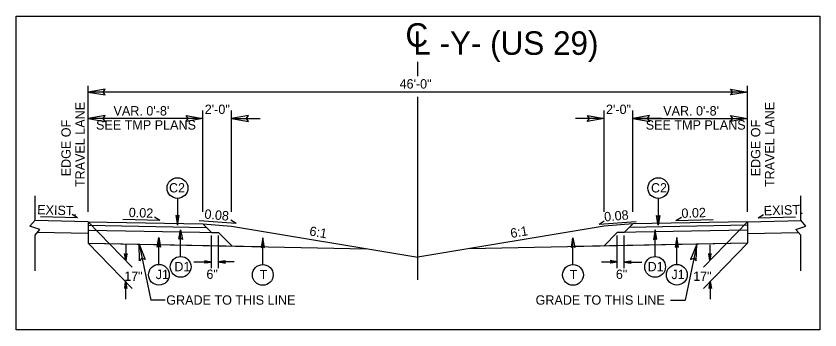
# Model space of a CAD drawing. Extents: x 1901582 to 1902252, y 193723 to 194156.
# Drawn here: x 1902149.6 to 1902205.7, y 193879 to 193901 of the extents above; entities that cross this region are included whole.
import ezdxf

# ---------------------------------------------------------------- set-up
doc = ezdxf.new("R2010")
doc.units = 0
for name, color, linetype in [('Old_Level_1', 7, 'Continuous'), ('Old_Level_11', 7, 'Continuous'), ('Old_Level_2', 7, 'Continuous'), ('Old_Level_20', 7, 'Continuous'), ('Prop Dimension', 7, 'Continuous'), ('Typical Pavement Slope Information CELL', 7, 'Continuous'), ('Typical Slope Point Local CELL', 7, 'Continuous'), ('Typical Terminator CELL', 7, 'Continuous'), ('Typical Text Asphalt at Bridge Approach CELL', 7, 'Continuous'), ('Typical Text Centerline CELL', 7, 'Continuous')]:
    doc.layers.add(name, color=color, linetype=linetype)

msp = doc.modelspace()

# ---------------------------------------------------------------- linework, layer by layer
at = {"layer": 'Old_Level_1'}
for p, q in [((1902164.598, 193893.8), (1902166.598, 193893.8)), ((1902190.598, 193893.8), (1902188.598, 193893.8)), ((1902194.598, 193893.8), (1902192.598, 193893.8)), ((1902154.598, 193886.59), (1902150.856, 193886.665)), ((1902200.599, 193886.59), (1902204.341, 193886.665)), ((1902154.598, 193886.59), (1902154.598, 193885.09)), ((1902154.598, 193886.59), (1902162.598, 193886.43)), ((1902154.598, 193886.59), (1902157.667, 193883.42)), ((1902154.598, 193886.34), (1902162.853, 193886.175)), ((1902162.598, 193886.43), (1902163.194, 193885.835)), ((1902162.598, 193886.43), (1902164.598, 193886.27)), ((1902164.598, 193886.27), (1902177.598, 193884.103)), ((1902190.599, 193886.27), (1902177.598, 193884.103)), ((1902192.599, 193886.43), (1902190.599, 193886.27)), ((1902192.599, 193886.43), (1902192.003, 193885.835)), ((1902200.599, 193886.34), (1902192.344, 193886.175)), ((1902200.599, 193886.59), (1902192.599, 193886.43)), ((1902200.599, 193886.59), (1902197.53, 193883.42)), ((1902200.599, 193886.59), (1902200.599, 193885.09)), ((1902154.598, 193885.756), (1902151.041, 193885.828)), ((1902154.598, 193886.007), (1902163.694, 193885.825)), ((1902163.194, 193885.835), (1902163.694, 193885.825)), ((1902163.694, 193885.825), (1902164.629, 193884.889)), ((1902191.503, 193885.825), (1902190.568, 193884.889)), ((1902200.599, 193886.007), (1902191.503, 193885.825)), ((1902192.003, 193885.835), (1902191.503, 193885.825)), ((1902200.599, 193885.756), (1902204.156, 193885.828)), ((1902154.598, 193885.09), (1902174.009, 193884.702)), ((1902154.598, 193885.09), (1902166.629, 193884.849)), ((1902154.598, 193885.09), (1902157.667, 193881.92)), ((1902158.136, 193885.019), (1902158.954, 193881.11)), ((1902200.599, 193885.09), (1902181.188, 193884.702)), ((1902200.599, 193885.09), (1902188.568, 193884.849)), ((1902197.061, 193885.019), (1902196.243, 193881.11)), ((1902200.599, 193885.09), (1902197.53, 193881.92)), ((1902157.218, 193884.972), (1902157.218, 193883.884)), ((1902197.979, 193884.972), (1902197.979, 193883.884)), ((1902157.218, 193883.884), (1902157.133, 193884.361)), ((1902157.145, 193884.352), (1902157.218, 193883.884)), ((1902157.218, 193883.884), (1902157.158, 193884.343)), ((1902157.17, 193884.335), (1902157.218, 193883.884)), ((1902157.218, 193883.884), (1902157.182, 193884.326)), ((1902157.194, 193884.317), (1902157.218, 193883.884)), ((1902157.218, 193883.884), (1902157.206, 193884.308)), ((1902157.218, 193883.884), (1902157.302, 193884.361)), ((1902157.218, 193883.884), (1902157.29, 193884.352)), ((1902157.278, 193884.343), (1902157.218, 193883.884)), ((1902157.218, 193883.884), (1902157.266, 193884.335)), ((1902157.254, 193884.326), (1902157.218, 193883.884)), ((1902157.218, 193883.884), (1902157.242, 193884.317)), ((1902157.23, 193884.308), (1902157.218, 193883.884)), ((1902157.218, 193884.299), (1902157.218, 193883.884)), ((1902163.694, 193883.786), (1902164.171, 193883.87)), ((1902163.694, 193883.786), (1902164.162, 193883.859)), ((1902191.503, 193883.786), (1902191.026, 193883.87)), ((1902191.503, 193883.786), (1902191.035, 193883.859)), ((1902197.979, 193883.884), (1902197.895, 193884.361)), ((1902197.979, 193883.884), (1902197.907, 193884.352)), ((1902197.919, 193884.343), (1902197.979, 193883.884)), ((1902197.979, 193883.884), (1902197.931, 193884.335)), ((1902197.943, 193884.326), (1902197.979, 193883.884)), ((1902197.979, 193883.884), (1902197.955, 193884.317)), ((1902197.967, 193884.308), (1902197.979, 193883.884)), ((1902197.979, 193883.884), (1902198.064, 193884.361)), ((1902198.052, 193884.352), (1902197.979, 193883.884)), ((1902197.979, 193883.884), (1902198.039, 193884.343)), ((1902198.027, 193884.335), (1902197.979, 193883.884)), ((1902197.979, 193883.884), (1902198.015, 193884.326)), ((1902198.003, 193884.317), (1902197.979, 193883.884)), ((1902197.979, 193883.884), (1902197.991, 193884.308)), ((1902197.979, 193884.299), (1902197.979, 193883.884)), ((1902163.194, 193883.769), (1902161.968, 193883.769)), ((1902163.194, 193883.769), (1902162.716, 193883.854)), ((1902163.194, 193883.769), (1902162.716, 193883.685)), ((1902162.726, 193883.842), (1902163.194, 193883.769)), ((1902163.194, 193883.769), (1902162.726, 193883.697)), ((1902163.194, 193883.769), (1902162.734, 193883.83)), ((1902162.734, 193883.71), (1902163.194, 193883.769)), ((1902162.744, 193883.818), (1902163.194, 193883.769)), ((1902163.194, 193883.769), (1902162.744, 193883.722)), ((1902163.194, 193883.769), (1902162.752, 193883.805)), ((1902162.752, 193883.734), (1902163.194, 193883.769)), ((1902162.76, 193883.793), (1902163.194, 193883.769)), ((1902163.194, 193883.769), (1902162.76, 193883.746)), ((1902163.194, 193883.769), (1902162.769, 193883.781)), ((1902162.769, 193883.758), (1902163.194, 193883.769)), ((1902164.153, 193883.847), (1902163.694, 193883.786)), ((1902163.694, 193883.786), (1902164.145, 193883.835)), ((1902164.136, 193883.822), (1902163.694, 193883.786)), ((1902163.694, 193883.786), (1902164.127, 193883.81)), ((1902164.118, 193883.798), (1902163.694, 193883.786)), ((1902164.782, 193883.786), (1902163.694, 193883.786)), ((1902163.694, 193883.786), (1902164.171, 193883.702)), ((1902164.162, 193883.713), (1902163.694, 193883.786)), ((1902163.694, 193883.786), (1902164.153, 193883.727)), ((1902164.145, 193883.739), (1902163.694, 193883.786)), ((1902163.694, 193883.786), (1902164.136, 193883.751)), ((1902164.127, 193883.762), (1902163.694, 193883.786)), ((1902163.694, 193883.786), (1902164.118, 193883.774)), ((1902164.109, 193883.786), (1902163.694, 193883.786)), ((1902190.415, 193883.786), (1902191.503, 193883.786)), ((1902191.503, 193883.786), (1902191.026, 193883.702)), ((1902191.035, 193883.713), (1902191.503, 193883.786)), ((1902191.044, 193883.847), (1902191.503, 193883.786)), ((1902191.503, 193883.786), (1902191.044, 193883.727)), ((1902191.503, 193883.786), (1902191.052, 193883.835)), ((1902191.052, 193883.739), (1902191.503, 193883.786)), ((1902191.061, 193883.822), (1902191.503, 193883.786)), ((1902191.503, 193883.786), (1902191.061, 193883.751)), ((1902191.503, 193883.786), (1902191.07, 193883.81)), ((1902191.07, 193883.762), (1902191.503, 193883.786)), ((1902191.079, 193883.798), (1902191.503, 193883.786)), ((1902191.503, 193883.786), (1902191.079, 193883.774)), ((1902191.088, 193883.786), (1902191.503, 193883.786)), ((1902192.003, 193883.769), (1902192.481, 193883.854)), ((1902192.471, 193883.842), (1902192.003, 193883.769)), ((1902192.003, 193883.769), (1902192.463, 193883.83)), ((1902192.453, 193883.818), (1902192.003, 193883.769)), ((1902192.003, 193883.769), (1902192.445, 193883.805)), ((1902192.437, 193883.793), (1902192.003, 193883.769)), ((1902192.003, 193883.769), (1902192.428, 193883.781)), ((1902192.003, 193883.769), (1902192.481, 193883.685)), ((1902192.428, 193883.758), (1902192.003, 193883.769)), ((1902192.003, 193883.769), (1902192.437, 193883.746)), ((1902192.445, 193883.734), (1902192.003, 193883.769)), ((1902192.003, 193883.769), (1902192.453, 193883.722)), ((1902192.463, 193883.71), (1902192.003, 193883.769)), ((1902192.003, 193883.769), (1902192.471, 193883.697)), ((1902192.003, 193883.769), (1902193.229, 193883.769)), ((1902157.201, 193882.401), (1902157.116, 193881.924)), ((1902157.201, 193882.401), (1902157.128, 193881.933)), ((1902157.141, 193881.942), (1902157.201, 193882.401)), ((1902157.201, 193882.401), (1902157.153, 193881.951)), ((1902157.165, 193881.959), (1902157.201, 193882.401)), ((1902157.201, 193882.401), (1902157.177, 193881.968)), ((1902157.189, 193881.977), (1902157.201, 193882.401)), ((1902157.201, 193882.401), (1902157.285, 193881.924)), ((1902157.273, 193881.933), (1902157.201, 193882.401)), ((1902157.201, 193882.401), (1902157.261, 193881.942)), ((1902157.249, 193881.951), (1902157.201, 193882.401)), ((1902157.201, 193882.401), (1902157.237, 193881.959)), ((1902157.225, 193881.968), (1902157.201, 193882.401)), ((1902157.201, 193882.401), (1902157.213, 193881.977)), ((1902157.201, 193882.401), (1902157.201, 193881.176)), ((1902197.996, 193882.401), (1902197.912, 193881.924)), ((1902197.924, 193881.933), (1902197.996, 193882.401)), ((1902197.996, 193882.401), (1902197.936, 193881.942)), ((1902197.948, 193881.951), (1902197.996, 193882.401)), ((1902197.996, 193882.401), (1902197.96, 193881.959)), ((1902197.972, 193881.968), (1902197.996, 193882.401)), ((1902197.996, 193882.401), (1902197.984, 193881.977)), ((1902197.996, 193882.401), (1902198.081, 193881.924)), ((1902198.008, 193881.977), (1902197.996, 193882.401)), ((1902197.996, 193882.401), (1902198.02, 193881.968)), ((1902198.032, 193881.959), (1902197.996, 193882.401)), ((1902197.996, 193882.401), (1902198.044, 193881.951)), ((1902198.056, 193881.942), (1902197.996, 193882.401)), ((1902197.996, 193882.401), (1902198.069, 193881.933)), ((1902197.996, 193882.401), (1902197.996, 193881.176)), ((1902159.963, 193881.11), (1902158.954, 193881.11)), ((1902195.234, 193881.11), (1902196.243, 193881.11))]:
    msp.add_line(p, q, dxfattribs=at)
msp.add_lwpolyline([(1902205.657, 193879.027), (1902149.557, 193879.027), (1902149.557, 193900.957), (1902205.657, 193900.957)], close=True, dxfattribs=at)
at = {"layer": 'Old_Level_11'}
for p, q in [((1902177.598, 193896.757), (1902177.598, 193897.749)), ((1902177.598, 193882.522), (1902177.598, 193895.313)), ((1902160.822, 193888.214), (1902160.822, 193886.34)), ((1902194.375, 193888.214), (1902194.375, 193886.34)), ((1902161.041, 193884.157), (1902161.041, 193886.032)), ((1902194.156, 193884.157), (1902194.156, 193886.032)), ((1902159.526, 193883.607), (1902159.526, 193885.482)), ((1902166.774, 193883.595), (1902166.774, 193885.469)), ((1902188.423, 193883.595), (1902188.423, 193885.469)), ((1902195.671, 193883.607), (1902195.671, 193885.482))]:
    msp.add_line(p, q, dxfattribs=at)
for points in [[(1902160.706, 193887.012), (1902160.822, 193886.34), (1902160.941, 193887.015), (1902160.822, 193886.93)], [(1902194.491, 193887.012), (1902194.375, 193886.34), (1902194.256, 193887.015), (1902194.375, 193886.93)], [(1902160.925, 193885.36), (1902161.041, 193886.032), (1902161.16, 193885.356), (1902161.041, 193885.442)], [(1902194.272, 193885.36), (1902194.156, 193886.032), (1902194.037, 193885.356), (1902194.156, 193885.442)], [(1902159.41, 193884.81), (1902159.526, 193885.482), (1902159.645, 193884.806), (1902159.526, 193884.892)], [(1902166.889, 193884.798), (1902166.774, 193885.469), (1902166.654, 193884.794), (1902166.774, 193884.88)], [(1902188.308, 193884.798), (1902188.423, 193885.469), (1902188.543, 193884.794), (1902188.423, 193884.88)], [(1902195.787, 193884.81), (1902195.671, 193885.482), (1902195.552, 193884.806), (1902195.671, 193884.892)]]:
    msp.add_lwpolyline(points, close=True, dxfattribs=at)
for centre in [(1902160.822, 193888.94), (1902194.375, 193888.94), (1902161.041, 193883.432), (1902194.156, 193883.432), (1902159.526, 193882.882), (1902166.773, 193882.87), (1902188.423, 193882.87), (1902195.671, 193882.882)]:
    msp.add_circle(centre, 0.725, dxfattribs=at)
at = {"layer": 'Prop Dimension'}
for p, q in [((1902154.598, 193887.282), (1902154.599, 193896.083)), ((1902200.598, 193895.651), (1902154.599, 193895.651)), ((1902200.599, 193887.282), (1902200.598, 193896.083)), ((1902162.598, 193887.282), (1902162.598, 193894.354)), ((1902164.598, 193887.282), (1902164.598, 193894.354)), ((1902190.599, 193887.282), (1902190.598, 193894.354)), ((1902192.599, 193887.282), (1902192.598, 193894.354)), ((1902162.598, 193893.8), (1902154.598, 193893.8)), ((1902192.598, 193893.8), (1902200.598, 193893.8)), ((1902163.194, 193883.332), (1902163.194, 193885.625)), ((1902163.694, 193883.332), (1902163.694, 193885.625)), ((1902191.503, 193883.332), (1902191.503, 193885.625)), ((1902192.003, 193883.332), (1902192.003, 193885.625))]:
    msp.add_line(p, q, dxfattribs=at)
at = {"layer": 'Typical Pavement Slope Information CELL'}
for p, q in [((1902153.844, 193886.861), (1902151.255, 193886.922)), ((1902153.844, 193886.861), (1902153.469, 193887.09)), ((1902159.586, 193886.684), (1902156.997, 193886.745)), ((1902159.586, 193886.684), (1902159.211, 193886.912)), ((1902164.908, 193886.453), (1902164.547, 193886.702)), ((1902195.611, 193886.684), (1902195.986, 193886.912)), ((1902195.611, 193886.684), (1902198.2, 193886.745)), ((1902201.353, 193886.861), (1902201.728, 193887.09)), ((1902201.353, 193886.861), (1902203.942, 193886.922)), ((1902164.908, 193886.453), (1902162.327, 193886.659)), ((1902190.247, 193886.406), (1902190.609, 193886.656)), ((1902190.247, 193886.406), (1902192.828, 193886.613))]:
    msp.add_line(p, q, dxfattribs=at)
at = {"layer": 'Typical Terminator CELL'}
for points in [[(1902155.77, 193895.853), (1902154.599, 193895.651), (1902155.777, 193895.443), (1902155.627, 193895.651)], [(1902199.427, 193895.853), (1902200.598, 193895.651), (1902199.42, 193895.443), (1902199.57, 193895.651)], [(1902155.77, 193894.002), (1902154.598, 193893.8), (1902155.777, 193893.592), (1902155.627, 193893.8)], [(1902161.427, 193894.002), (1902162.598, 193893.8), (1902161.42, 193893.592), (1902161.57, 193893.8)], [(1902165.77, 193894.002), (1902164.598, 193893.8), (1902165.777, 193893.592), (1902165.627, 193893.8)], [(1902189.427, 193894.002), (1902190.598, 193893.8), (1902189.42, 193893.592), (1902189.57, 193893.8)], [(1902193.77, 193894.002), (1902192.598, 193893.8), (1902193.777, 193893.592), (1902193.627, 193893.8)], [(1902199.427, 193894.002), (1902200.598, 193893.8), (1902199.42, 193893.592), (1902199.57, 193893.8)], [(1902158.178, 193883.863), (1902158.136, 193885.019), (1902158.569, 193883.939), (1902158.341, 193884.04)], [(1902197.019, 193883.863), (1902197.061, 193885.019), (1902196.628, 193883.939), (1902196.856, 193884.04)]]:
    msp.add_lwpolyline(points, close=True, dxfattribs=at)
at = {"layer": 'Typical Text Asphalt at Bridge Approach CELL'}
for points in [[(1902150.88, 193883.166), (1902150.88, 193885.64), (1902151.221, 193886.037), (1902150.525, 193886.279), (1902150.88, 193886.692), (1902150.884, 193888.395)], [(1902204.317, 193883.166), (1902204.317, 193885.64), (1902203.976, 193886.037), (1902204.672, 193886.279), (1902204.317, 193886.692), (1902204.313, 193888.395)]]:
    msp.add_lwpolyline(points, dxfattribs=at)

# ---------------------------------------------------------------- texts
at = {"layer": 'Old_Level_1'}
for s, p in [('46\'-0"', (1902176.319, 193895.891)), ("VAR. 0'-8'", (1902156.357, 193894.008)), ('2\'-0"', (1902162.726, 193894.114)), ('2\'-0"', (1902190.727, 193894.114)), ("VAR. 0'-8'", (1902194.72, 193894.008)), ('SEE TMP PLANS', (1902155.138, 193893.024)), ('SEE TMP PLANS', (1902193.501, 193893.024)), ('GRADE TO THIS LINE', (1902160.039, 193880.79)), ('GRADE TO THIS LINE', (1902185.813, 193880.79))]:
    msp.add_text(s, height=0.656, dxfattribs=at).set_placement(p)
for s, p in [('TRAVEL LANE', (1902154.355, 193889.009)), ('TRAVEL LANE', (1902202.482, 193889.009)), ('EDGE OF', (1902153.371, 193889.76)), ('EDGE OF', (1902201.498, 193889.76))]:
    msp.add_text(s, height=0.656, rotation=90, dxfattribs=at).set_placement(p)
at = {"layer": 'Old_Level_2'}
for s, rotation, p in [('EXIST.', 358.0279, (1902151.023, 193887.113)), ('0.02', 358.0279, (1902157.412, 193886.914)), ('0.08', 354.8109, (1902162.681, 193886.811)), ('0.08', 5.1891, (1902190.629, 193886.597)), ('0.02', 1.9721, (1902196.003, 193886.852)), ('EXIST.', 1.9721, (1902201.745, 193887.029))]:
    msp.add_text(s, height=0.656, rotation=rotation, dxfattribs=at).set_placement(p)
at = {"layer": 'Old_Level_20'}
for s, height, p in [('C2', 0.6491, (1902160.233, 193888.633)), ('C2', 0.6491, (1902193.869, 193888.633)), ('D1', 0.6491, (1902160.607, 193883.128)), ('D1', 0.6491, (1902193.635, 193883.128)), ('17"', 0.6491, (1902157.111, 193882.458)), ('J1', 0.6491, (1902159.308, 193882.579)), ('6"', 0.6491, (1902162.842, 193882.596)), ('T', 0.649, (1902166.563, 193882.577)), ('T', 0.649, (1902188.196, 193882.577)), ('6"', 0.6491, (1902191.419, 193882.596)), ('J1', 0.6491, (1902195.296, 193882.579)), ('17"', 0.6491, (1902196.818, 193882.458))]:
    msp.add_text(s, height=height, dxfattribs=at).set_placement(p)
at = {"layer": 'Typical Slope Point Local CELL'}
for rotation, p in [(350.1856, (1902169.992, 193885.633)), (9.8144, (1902184.113, 193885.444))]:
    msp.add_text('6:1', height=0.656, rotation=rotation, dxfattribs=at).set_placement(p)
at = {"layer": 'Typical Text Centerline CELL'}
msp.add_text('C', height=1.64, dxfattribs=at).set_placement((1902176.73, 193898.817))
msp.add_text('L -Y- (US 29)', height=1.64109, rotation=359.9469, dxfattribs=at).set_placement((1902177.276, 193898.257))

doc.saveas('drawing.dxf')
